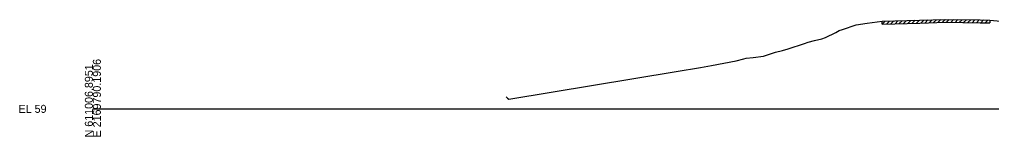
# Model space of a CAD drawing. Extents: x -26 to 6803, y -10 to 19606.
# Drawn here: x 1974.3 to 2314.5, y 6490.3 to 6531.3 of the extents above; entities that cross this region are included whole.
import ezdxf

# ---------------------------------------------------------------- set-up
doc = ezdxf.new("R2010")
doc.units = 0
for name, color, linetype in [('RD_GPK_XS_Cell', 7, 'Continuous'), ('RD_XS_ExGround', 7, 'Continuous'), ('RD_XS_ExPaveRet', 7, 'Continuous')]:
    doc.layers.add(name, color=color, linetype=linetype)

msp = doc.modelspace()

# ---------------------------------------------------------------- linework, layer by layer
at = {"layer": 'RD_GPK_XS_Cell'}
msp.add_line((2000, 6500), (2400, 6500), dxfattribs=at)
at = {"layer": 'RD_XS_ExGround'}
msp.add_lwpolyline([(2144.6, 6504.17), (2145.06, 6503.72), (2145.58, 6503.44), (2204.18, 6513.06), (2212.7, 6514.47), (2216.46, 6515.18), (2225.15, 6516.86), (2227.84, 6517.56), (2228.67, 6517.77), (2231.14, 6518), (2234.69, 6518.47), (2235.78, 6518.77), (2238.87, 6519.86), (2241.33, 6520.49), (2243.4, 6521.04), (2249.01, 6522.84), (2250.39, 6523.33), (2252.62, 6523.92), (2255.07, 6524.54), (2256.36, 6525.04), (2260, 6526.73), (2261.21, 6527.44), (2262.41, 6527.84), (2267.15, 6529.46), (2270.98, 6529.99), (2276.24, 6530.66), (2289.37, 6531.05), (2298.43, 6531.31), (2310.55, 6531.14), (2313.98, 6531.09), (2324.32, 6530.15)], dxfattribs=at)
at = {"layer": 'RD_XS_ExPaveRet'}
for p, q in [((2276.24, 6529.66), (2277.27, 6530.69)), ((2276.24, 6529.66), (2276.24, 6530.66)), ((2276.24, 6529.66), (2289.37, 6530.05)), ((2277.74, 6529.71), (2278.77, 6530.74)), ((2279.24, 6529.75), (2280.27, 6530.78)), ((2280.74, 6529.8), (2281.77, 6530.83)), ((2282.24, 6529.84), (2283.27, 6530.87)), ((2283.74, 6529.88), (2284.77, 6530.91)), ((2285.24, 6529.93), (2286.27, 6530.96)), ((2286.74, 6529.97), (2287.77, 6531)), ((2288.24, 6530.02), (2289.27, 6531.05)), ((2289.37, 6530.05), (2298.43, 6530.31)), ((2289.74, 6530.06), (2290.77, 6531.09)), ((2291.24, 6530.1), (2292.27, 6531.13)), ((2292.74, 6530.15), (2293.77, 6531.18)), ((2294.24, 6530.19), (2295.27, 6531.22)), ((2295.74, 6530.23), (2296.77, 6531.26)), ((2297.24, 6530.28), (2298.27, 6531.31)), ((2298.43, 6530.31), (2310.55, 6530.14)), ((2298.74, 6530.31), (2299.73, 6531.29)), ((2300.24, 6530.29), (2301.23, 6531.27)), ((2301.74, 6530.27), (2302.73, 6531.25)), ((2303.24, 6530.25), (2304.23, 6531.23)), ((2304.74, 6530.22), (2305.73, 6531.21)), ((2306.24, 6530.2), (2307.23, 6531.19)), ((2307.74, 6530.18), (2308.73, 6531.17)), ((2309.24, 6530.16), (2310.23, 6531.15)), ((2310.55, 6530.14), (2313.98, 6530.09)), ((2310.74, 6530.14), (2311.73, 6531.13)), ((2312.24, 6530.12), (2313.23, 6531.1)), ((2313.98, 6531.09), (2313.98, 6530.09))]:
    msp.add_line(p, q, dxfattribs=at)

# ---------------------------------------------------------------- texts
at = {"layer": 'RD_GPK_XS_Cell'}
for s, p in [('N 611006.8951', (2000, 6490)), ('E 2169790.1906', (2002.8, 6490))]:
    msp.add_text(s, height=2.8, rotation=90, dxfattribs=at).set_placement(p)
msp.add_text('EL 59', height=2.8, dxfattribs=at).set_placement((1974, 6498.6))

doc.saveas('drawing.dxf')
